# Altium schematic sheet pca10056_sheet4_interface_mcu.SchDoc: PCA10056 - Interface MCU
size A3; Organization: Nordic Semiconductor; DocumentNumber: 4; SheetNumber: 4; SheetTotal: 7; CompanyName: Nordic Semiconductor
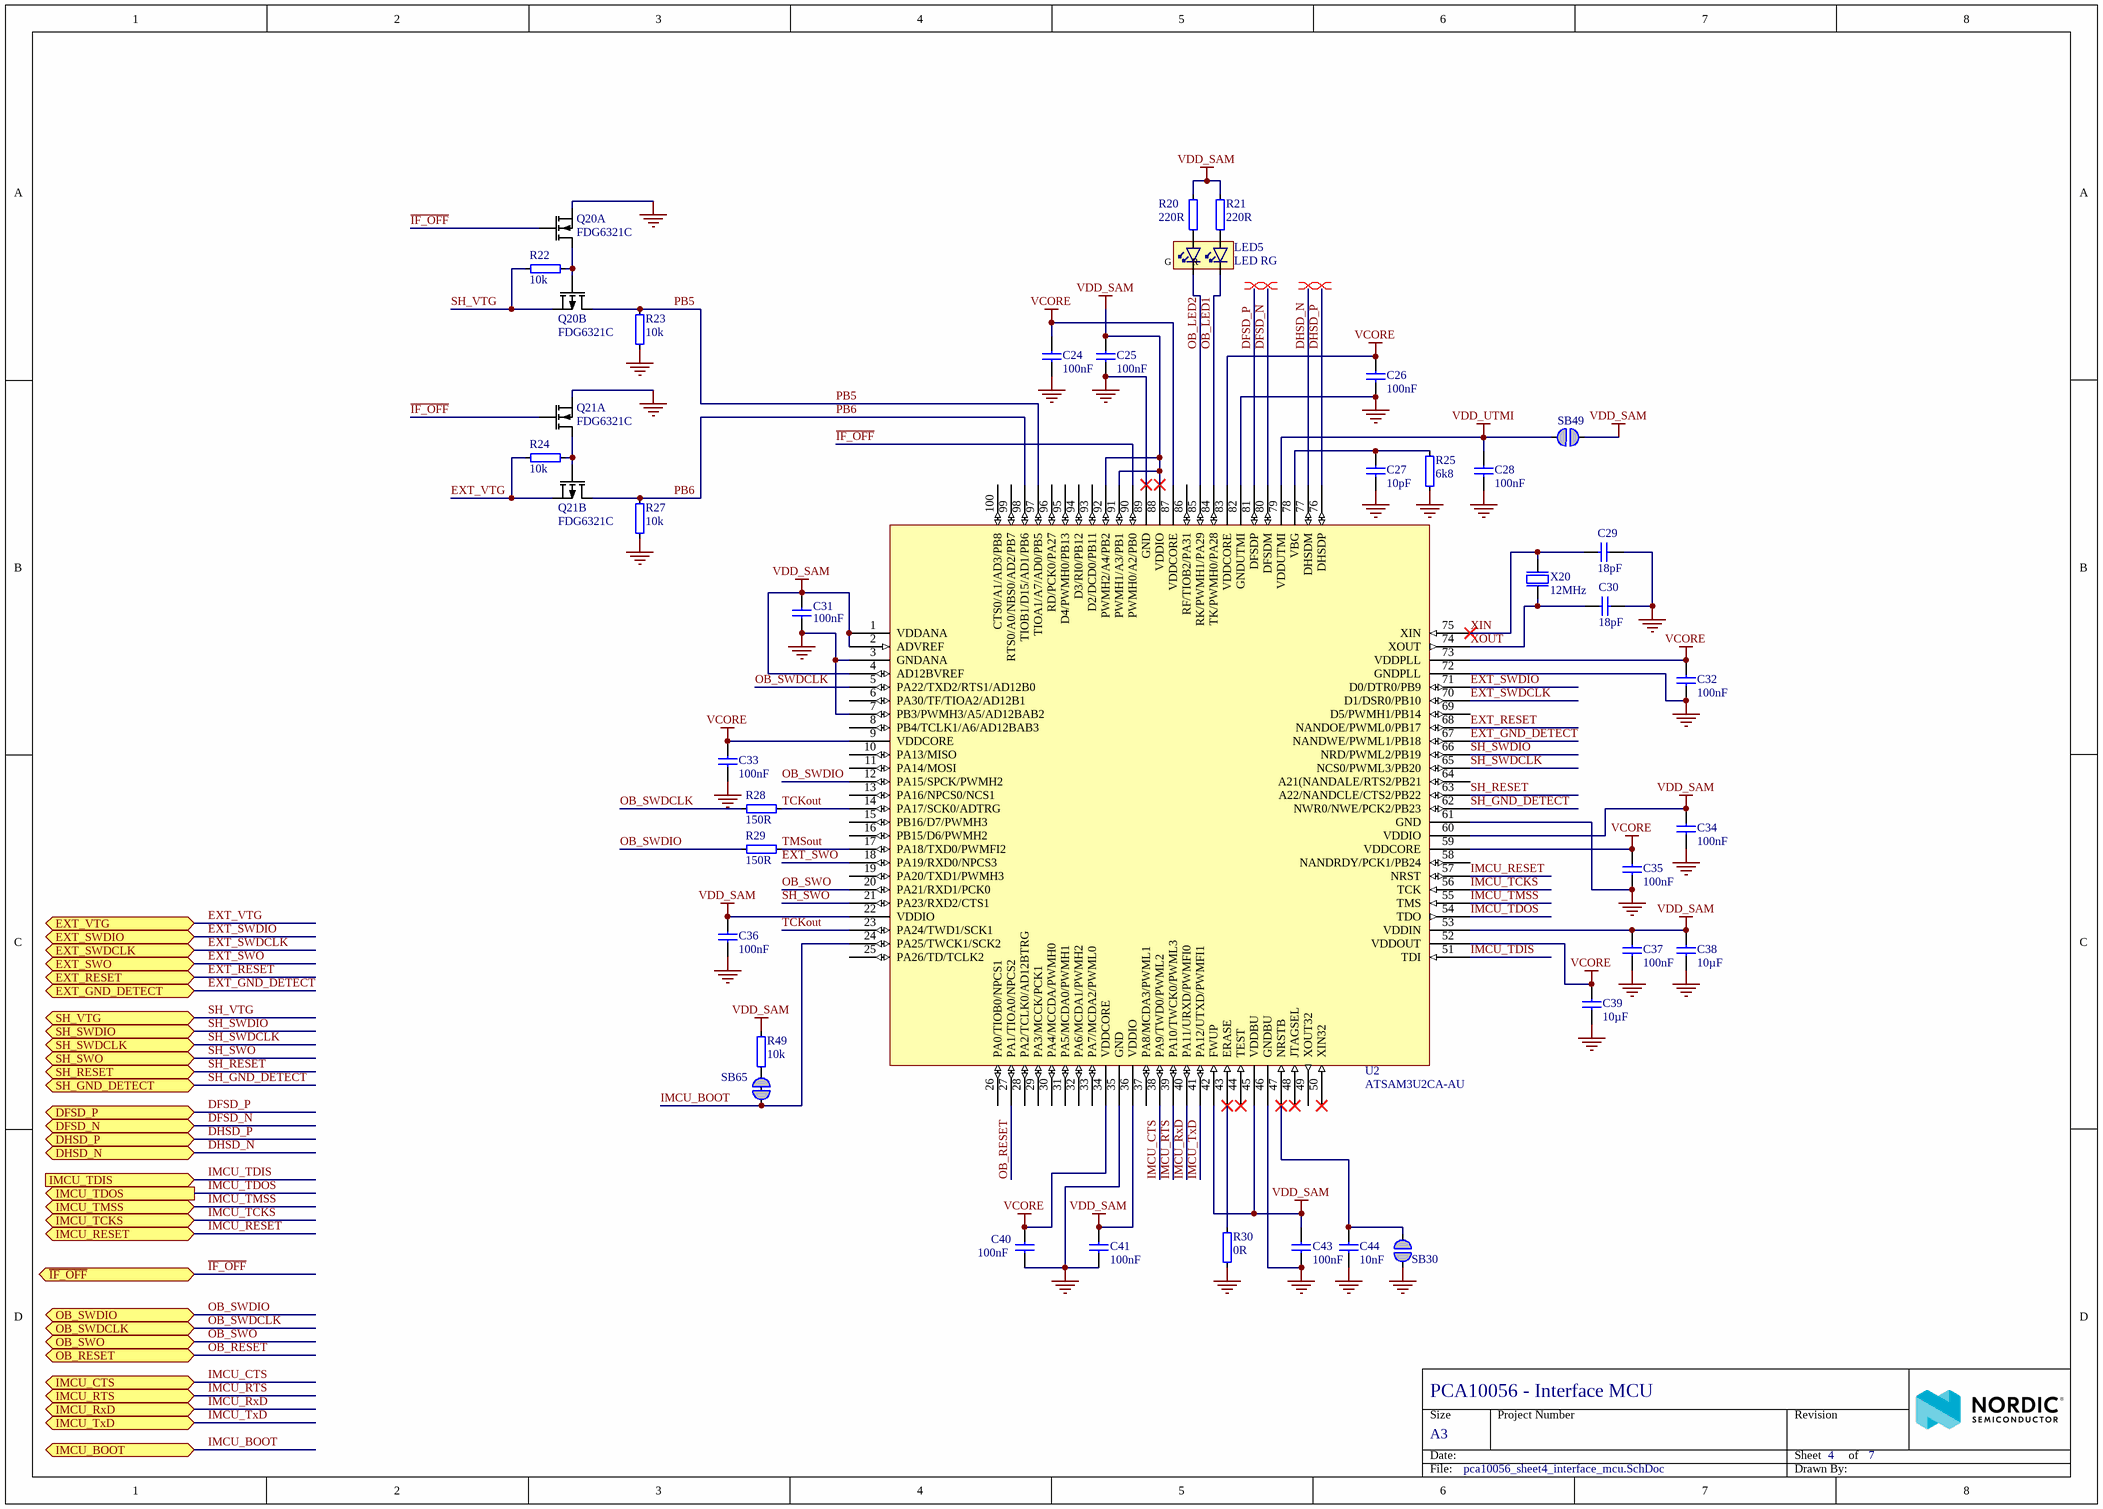
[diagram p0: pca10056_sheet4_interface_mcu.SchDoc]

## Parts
C24  100nF  [CAPC1005X04L]
C25  100nF  [CAPC1005X04L]
C26  100nF  [CAPC1005X04L]
C27  10pF  [CAPC1005X04L]
C28  100nF  [CAPC1005X04L]
C29  18pF  [CAPC1005X04L]
C30  18pF  [CAPC1005X04L]
C31  100nF  [CAPC1005X04L]
C32  100nF  [CAPC1005X04L]
C33  100nF  [CAPC1005X04L]
C34  100nF  [CAPC1005X04L]
C35  100nF  [CAPC1005X04L]
C36  100nF  [CAPC1005X04L]
C37  100nF  [CAPC1005X04L]
C38  10µF  [CAPC1608X06L]
C39  10µF  [CAPC1608X06L]
C40  100nF  [CAPC1005X04L]
C41  100nF  [CAPC1005X04L]
C43  100nF  [CAPC1005X04L]
C44  10nF  [CAPC1005X04L]
LED5  LED RG  [LED_DUAL_0606]
Q20  FDG6321C  [SOT65P210X100-6N]  (parts A,B of 2)
Q21  FDG6321C  [SOT65P210X100-6N]  (parts A,B of 2)
R20  220R  [RESC1005X04L]
R21  220R  [RESC1005X04L]
R22  10k  [RESC1005X04L]
R23  10k  [RESC1005X04L]
R24  10k  [RESC1005X04L]
R25  6k8  [RESC1005X04L]
R27  10k  [RESC1005X04L]
R28  150R  [RESC1005X04L]
R29  150R  [RESC1005X04L]
R30  0R  [RESC1005X04L]
R49  10k  [RESC1005X04L]
SB30  Solderbridge  [Solderbridge]  (value not drawn)  (no BOM)
SB49  Solderbridge  [Solderbridge]  (value not drawn)  (no BOM)
SB65  Solderbridge  [Solderbridge_Shorted]  (value not drawn)  (net tie, no BOM)
U2  ATSAM3U2CA-AU  [TSQFP50P1600X1600X160-100N]
X20  12MHz  [BT-XTAL_3225]

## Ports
DFSD_N (bidir), DFSD_P (bidir), DHSD_N (bidir), DHSD_P (bidir), EXT_GND_DETECT (bidir), EXT_RESET (bidir), EXT_SWDCLK (bidir), EXT_SWDIO (bidir), EXT_SWO (bidir), EXT_VTG (bidir), IMCU_BOOT (bidir), IMCU_CTS (bidir), IMCU_RESET (bidir), IMCU_RTS (bidir), IMCU_RxD (bidir), IMCU_TCKS (bidir), IMCU_TDIS (in), IMCU_TDOS (out), IMCU_TMSS (bidir), IMCU_TxD (bidir), OB_RESET (bidir), OB_SWDCLK (bidir), OB_SWDIO (bidir), OB_SWO (bidir), SH_GND_DETECT (bidir), SH_RESET (bidir), SH_SWDCLK (bidir), SH_SWDIO (bidir), SH_SWO (bidir), SH_VTG (bidir), ~{IF_OFF} (bidir)

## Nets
GND: C24.1 C25.1 C26.1 C27.1 C28.1 C29.2 C30.2 C31.1 C32.2 C33.1 C34.1 C35.1 C36.1 C37.1 C38.1 C39.1 C40.1 C41.1 C43.1 C44.1 Q20.1(S1) Q21.1(S1) R23.1 R25.1 R27.1 R30.1 SB30.2 U2.3(GNDANA) U2.7(PB3/PWMH3/A5/AD12BAB2) U2.35(GND) U2.46(GNDBU) U2.61(GND) U2.72(GNDPLL) U2.82(GNDUTMI) U2.89(GND) X20.2(GND) X20.4(GND)
VCORE: C24.2 C26.2 C32.1 C33.2 C35.2 C39.2 C40.2 U2.9(VDDCORE) U2.34(VDDCORE) U2.52(VDDOUT) U2.59(VDDCORE) U2.73(VDDPLL) U2.83(VDDCORE) U2.87(VDDCORE)
VDD_SAM: C25.2 C31.2 C34.2 C36.2 C37.2 C38.2 C41.2 C43.2 R20.2 R21.2 R49.2 SB49.1 U2.1(VDDANA) U2.2(ADVREF) U2.4(AD12BVREF) U2.22(VDDIO) U2.36(VDDIO) U2.42(FWUP) U2.45(VDDBU) U2.53(VDDIN) U2.60(VDDIO) U2.88(VDDIO) U2.91(PWMH1/A3/PB1) U2.92(PWMH2/A4/PB2)
VDD_UTMI: C28.2 SB49.2 U2.79(VDDUTMI)
DFSD_N: U2.80(DFSDM) ; port DFSD_N
DFSD_P: U2.81(DFSDP) ; port DFSD_P
DHSD_N: U2.77(DHSDM) ; port DHSD_N
DHSD_P: U2.76(DHSDP) ; port DHSD_P
EXT_GND_DETECT: U2.67(NANDWE/PWML1/PB18) ; port EXT_GND_DETECT
EXT_RESET: U2.68(NANDOE/PWML0/PB17) ; port EXT_RESET
EXT_SWDCLK: U2.70(D1/DSR0/PB10) ; port EXT_SWDCLK
EXT_SWDIO: U2.71(D0/DTR0/PB9) ; port EXT_SWDIO
EXT_SWO: U2.18(PA19/RXD0/NPCS3) ; port EXT_SWO
EXT_VTG: Q21.4(S2) R24.1 ; port EXT_VTG
~{IF_OFF}: Q20.2(G1) Q21.2(G1) U2.90(PWMH0/A2/PB0) ; port ~{IF_OFF}
IMCU_BOOT: SB65.1 U2.24(PA25/TWCK1/SCK2) ; port IMCU_BOOT
IMCU_CTS: U2.38(PA9/TWD0/PWML2) ; port IMCU_CTS
IMCU_RESET: U2.57(NRST) ; port IMCU_RESET
IMCU_RTS: U2.39(PA10/TWCK0/PWML3) ; port IMCU_RTS
IMCU_RxD: U2.40(PA11/URXD/PWMFI0) ; port IMCU_RxD
IMCU_TCKS: U2.56(TCK) ; port IMCU_TCKS
IMCU_TDIS: U2.51(TDI) ; port IMCU_TDIS
IMCU_TDOS: U2.54(TDO) ; port IMCU_TDOS
IMCU_TMSS: U2.55(TMS) ; port IMCU_TMSS
IMCU_TxD: U2.41(PA12/UTXD/PWMFI1) ; port IMCU_TxD
OB_LED1: LED5.4(C1) U2.84(TK/PWMH0/PA28)
OB_LED2: LED5.3(C2) U2.85(RK/PWMH1/PA29)
OB_RESET: U2.27(PA1/TIOA0/NPCS2) ; port OB_RESET
OB_SWDCLK: R28.2 U2.5(PA22/TXD2/RTS1/AD12B0) ; port OB_SWDCLK
OB_SWDIO: R29.2 U2.12(PA15/SPCK/PWMH2) ; port OB_SWDIO
OB_SWO: U2.20(PA21/RXD1/PCK0) ; port OB_SWO
PB5: Q20.3(D2) R23.2 U2.97(TIOA1/A7/AD0/PB5)
PB6: Q21.3(D2) R27.2 U2.98(TIOB1/D15/AD1/PB6)
SH_GND_DETECT: U2.62(NWR0/NWE/PCK2/PB23) ; port SH_GND_DETECT
SH_RESET: U2.63(A22/NANDCLE/CTS2/PB22) ; port SH_RESET
SH_SWDCLK: U2.65(NCS0/PWML3/PB20) ; port SH_SWDCLK
SH_SWDIO: U2.66(NRD/PWML2/PB19) ; port SH_SWDIO
SH_SWO: U2.21(PA23/RXD2/CTS1) ; port SH_SWO
SH_VTG: Q20.4(S2) R22.1 ; port SH_VTG
TCKout: R28.1 U2.14(PA17/SCK0/ADTRG) U2.23(PA24/TWD1/SCK1)
TMSout: R29.1 U2.17(PA18/TXD0/PWMFI2)
XIN: C29.1 U2.75(XIN) X20.3(out)
XOUT: C30.1 U2.74(XOUT) X20.1(inp)
NetC27_2: C27.2 R25.2 U2.78(VBG)
NetC44_2: C44.2 SB30.1 U2.47(NRSTB)
NetLED5_1: LED5.1(A2) R20.1
NetLED5_2: LED5.2(A1) R21.1
NetQ20_5: Q20.5(G2) Q20.6(D1) R22.2
NetQ21_5: Q21.5(G2) Q21.6(D1) R24.2
NetR30_2: R30.2 U2.43(ERASE)
NetR49_1: R49.1 SB65.2

Not connected (* = marked no-connect by the designer): U2 6(PA30/TF/TIOA2/AD12B1) 8(PB4/TCLK1/A6/AD12BAB3) 10(PA13/MISO) 11(PA14/MOSI) 13(PA16/NPCS0/NCS1) 15(PB16/D7/PWMH3) 16(PB15/D6/PWMH2) 19(PA20/TXD1/PWMH3) 25(PA26/TD/TCLK2) 26(PA0/TIOB0/NPCS1) 28(PA2/TCLK0/AD12BTRG) 29(PA3/MCCK/PCK1) 30(PA4/MCCDA/PWMH0) 31(PA5/MCDA0/PWMH1) 32(PA6/MCDA1/PWMH2) 33(PA7/MCDA2/PWML0) 37(PA8/MCDA3/PWML1) 44(TEST)* 48(JTAGSEL)* 49(XOUT32) 50(XIN32)* 58(NANDRDY/PCK1/PB24) 64(A21(NANDALE/RTS2/PB21) 69(D5/PWMH1/PB14) 86(RF/TIOB2/PA31) 93(D2/DCD0/PB11) 94(D3/RI0/PB12) 95(D4/PWMH0/PB13) 96(RD/PCK0/PA27) 99(RTS0/A0/NBS0/AD2/PB7) 100(CTS0/A1/AD3/PB8)

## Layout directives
differential pair: DFSD_N, DFSD_P, DHSD_N, DHSD_P

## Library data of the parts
C24-C26 C28 C31-C37 C40 C41 C43 = C0402-100n: Capacitor, X7R, ±10%; Part number IPS: 00000005296; Note: 16V; Artikkelnr Noca: 20039200; Artikkelnr Simpro: N.A.
C27 = C0402-10p: Capacitor, NP0, ±2%; 2nd source part number: 185-6064; Note: 50V; Artikkelnr Noca: 20029260; Artikkelnr Simpro: N.A.
C29 C30 = C0402-18p: Capacitor, NP0, ±5%; Note: 50V; Artikkelnr Noca: 20029209; Artikkelnr Simpro: N.A.
C38 C39 = C0603-10µ: Capacitor, X5R, ±20%; Part number IPS: 00000007785; Note: 6.3V; Artikkelnr Noca: 20039234; Artikkelnr Simpro: N.A.
C44 = C0402-10n: Capacitor, X7R, ±10%; Part number IPS: 00000007784; Note: 16V; Artikkelnr Noca: 20039166; Artikkelnr Simpro: N.A.
LED5 = LTST-C195KGJRKT: Ultra bright AlInGaP Bi-Color LED; Manufacturer: Lite-On Inc; 2nd source part number: 859-LTST-C195KGJRKT; Artikkelnr Noca: 13019145; Artikkelnr Simpro: N.A.
Q20 Q21 = FDG6321C: Fairchild, FDG6321C, Dual N & P Channel Digital FET; 2nd source part number: FDG6321CCT-ND; Artikkelnr Noca: 35029089; Artikkelnr Simpro: N.A.
R20 R21 = R0402-220: Resistor, ±1%, 0.063W; Note: Chip Res 1%; Artikkelnr Noca: 27049057; Artikkelnr Simpro: N.A.; Value Ohm: 220
R22-R24 R27 R49 = R0402-10k: Resistor, ±1%, 0.063W; Part number IPS: 00000002093; Note: Chip Res 1%; Artikkelnr Noca: 27049097; Artikkelnr Simpro: N.A.; Value Ohm: 10000
R25 = R0402-6k8: Resistor, ±1%, 0.063W; Note: Chip Res 1%; Artikkelnr Noca: 27049093; Artikkelnr Simpro: N.A.; Value Ohm: 6800
R28 R29 = R0402-150: Resistor, ±1%, 0.063W; Note: Chip Res 1%; Artikkelnr Noca: 27049053; Artikkelnr Simpro: N.A.; Value Ohm: 150
R30 = R0402-0R: Resistor, ±5%, 0.063W; Note: Chip Res 5%; Artikkelnr Noca: 27049000; Artikkelnr Simpro: N.A.; Value Ohm: 0
SB30 SB49 = Solderbridge: Artikkelnr Noca: N.A.
SB65 = Solderbridge Shorted: Shorted Solderbridge; Artikkelnr Noca: N.A.
U2 = ATSAM3U2CA-AU: IC MCU 32bit 128kB flash 100LQFP; Manufacturer: Atmel; 2nd source part number: 184-1662; Artikkelnr Noca: 15019073; Artikkelnr Simpro: N.A.
X20 = XTAL_SMD3225_12MHz_18pF_TXC: XTAL SMD 3225, 12MHz, Cl=18pF, Tol: ±30ppm, Stab: ±30ppm; Manufacturer: TXC Corporation; Manufacturer Part Number: 7M-12.000MAAJ-T; 2nd source part number: 184-2056; Note: XTAL SMD 12.000MHz; Artikkelnr Noca: 22019166; Artikkelnr Simpro: N.A.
